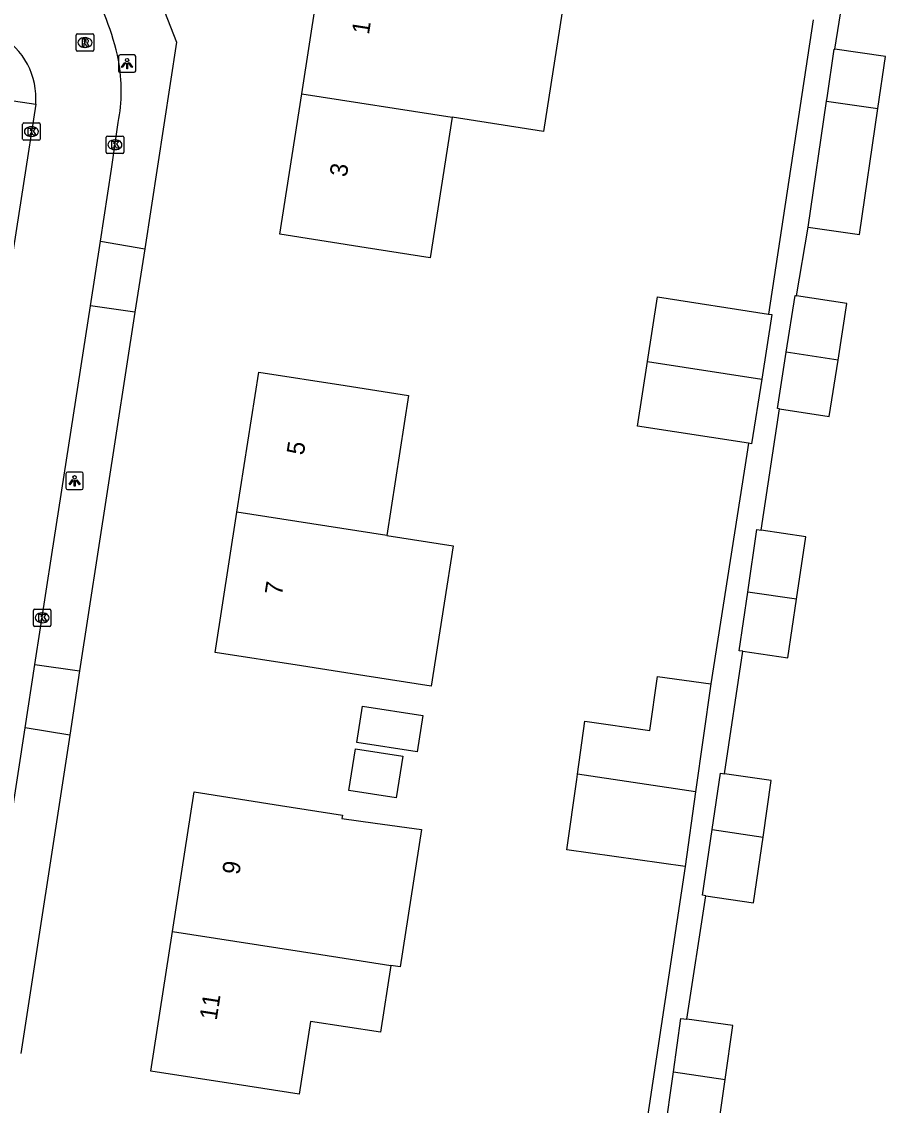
# Model space of a CAD drawing. Extents: x 161486 to 162249, y 379484 to 380829.
# Drawn here: x 162087.4 to 162137.6, y 380409.6 to 380471.6 of the extents above; entities that cross this region are included whole.
import ezdxf

# ---------------------------------------------------------------- set-up
doc = ezdxf.new("R2010")
doc.units = 0
for name, color, linetype in [('IMGEO_Kolk', 7, 'Continuous'), ('IMGEO_Lichtpunt', 7, 'Continuous'), ('IMGEO_Pand', 7, 'Continuous'), ('IMGEO_Pand_nummerreeks', 7, 'Continuous'), ('IMGEO_Rijbaan_lokaal_open', 7, 'Continuous'), ('IMGEO_Rioolput', 7, 'Continuous'), ('IMGEO_Voetpad_open', 7, 'Continuous')]:
    doc.layers.add(name, color=color, linetype=linetype)

msp = doc.modelspace()

# ---------------------------------------------------------------- linework, layer by layer
at = {"layer": 'IMGEO_Kolk'}
for p, q in [((162087.491, 380465.787), (162088.343, 380465.787)), ((162087.416, 380464.861), (162087.416, 380465.713)), ((162087.904, 380465.567), (162087.929, 380465.567)), ((162088.417, 380465.713), (162088.417, 380464.861)), ((162088.343, 380464.787), (162087.491, 380464.787)), ((162087.927, 380465.007), (162087.902, 380465.007)), ((162092.2, 380464.107), (162092.2, 380464.959)), ((162092.275, 380465.033), (162093.127, 380465.033)), ((162092.688, 380464.813), (162092.713, 380464.813)), ((162093.201, 380464.959), (162093.201, 380464.107)), ((162093.127, 380464.033), (162092.275, 380464.033)), ((162092.711, 380464.253), (162092.686, 380464.253)), ((162088.03, 380437.037), (162088.03, 380437.889)), ((162088.105, 380437.963), (162088.957, 380437.963)), ((162089.031, 380437.889), (162089.031, 380437.037)), ((162088.518, 380437.743), (162088.543, 380437.743)), ((162088.957, 380436.963), (162088.105, 380436.963)), ((162088.541, 380437.183), (162088.516, 380437.183))]:
    msp.add_line(p, q, dxfattribs=at)
for points in [[(162087.491, 380465.787), (162088.343, 380465.787)], [(162087.416, 380464.861), (162087.416, 380465.713)], [(162087.737, 380465.487), (162087.86, 380465.487), (162087.86, 380465.336), (162087.99, 380465.487), (162088.154, 380465.487), (162088.008, 380465.336), (162088.161, 380465.087), (162088.009, 380465.087), (162087.924, 380465.251), (162087.86, 380465.184), (162087.86, 380465.087), (162087.737, 380465.087), (162087.737, 380465.487)], [(162088.417, 380465.713), (162088.417, 380464.861)], [(162088.343, 380464.787), (162087.491, 380464.787)], [(162092.2, 380464.107), (162092.2, 380464.959)], [(162092.275, 380465.033), (162093.127, 380465.033)], [(162092.521, 380464.733), (162092.644, 380464.733), (162092.644, 380464.582), (162092.774, 380464.733), (162092.938, 380464.733), (162092.792, 380464.582), (162092.945, 380464.333), (162092.793, 380464.333), (162092.708, 380464.497), (162092.644, 380464.43), (162092.644, 380464.333), (162092.521, 380464.333), (162092.521, 380464.733)], [(162093.201, 380464.959), (162093.201, 380464.107)], [(162093.127, 380464.033), (162092.275, 380464.033)], [(162088.03, 380437.037), (162088.03, 380437.889)], [(162088.105, 380437.963), (162088.957, 380437.963)], [(162089.031, 380437.889), (162089.031, 380437.037)], [(162088.351, 380437.663), (162088.474, 380437.663), (162088.474, 380437.512), (162088.604, 380437.663), (162088.768, 380437.663), (162088.622, 380437.512), (162088.775, 380437.263), (162088.623, 380437.263), (162088.538, 380437.427), (162088.474, 380437.36), (162088.474, 380437.263), (162088.351, 380437.263), (162088.351, 380437.663)], [(162088.957, 380436.963), (162088.105, 380436.963)]]:
    msp.add_lwpolyline(points, dxfattribs=at)
for centre, start, end in [((162087.493, 380465.711), 91.55205, 178.44795), ((162087.493, 380465.711), 91.55205, 178.44795), ((162088.341, 380465.711), 1.55205, 88.44795), ((162088.341, 380465.711), 1.55205, 88.44795), ((162087.493, 380464.863), 181.55205, 268.44795), ((162087.493, 380464.863), 181.55205, 268.44795), ((162088.341, 380464.863), 271.55205, 358.44795), ((162088.341, 380464.863), 271.55205, 358.44795), ((162092.277, 380464.957), 91.55205, 178.44795), ((162092.277, 380464.957), 91.55205, 178.44795), ((162093.125, 380464.957), 1.55205, 88.44795), ((162093.125, 380464.957), 1.55205, 88.44795), ((162092.277, 380464.109), 181.55205, 268.44795), ((162092.277, 380464.109), 181.55205, 268.44795), ((162093.125, 380464.109), 271.55205, 358.44795), ((162093.125, 380464.109), 271.55205, 358.44795), ((162088.107, 380437.887), 91.55205, 178.44795), ((162088.107, 380437.887), 91.55205, 178.44795), ((162088.955, 380437.887), 1.55205, 88.44795), ((162088.955, 380437.887), 1.55205, 88.44795), ((162088.107, 380437.039), 181.55205, 268.44795), ((162088.107, 380437.039), 181.55205, 268.44795), ((162088.955, 380437.039), 271.55205, 358.44795), ((162088.955, 380437.039), 271.55205, 358.44795)]:
    msp.add_arc(centre, 0.0765, start, end, dxfattribs=at)
for centre, major_axis, ratio, start_param, end_param in [((162087.903, 380465.287), (-0.387, 0.002), 0.722429, 4.712389, 7.853982), ((162087.928, 380465.287), (-0.39, 0.002), 0.717154, 1.570796, 4.712389), ((162092.687, 380464.533), (-0.387, 0.002), 0.722429, 4.712389, 7.853982), ((162092.712, 380464.533), (-0.39, 0.002), 0.717154, 1.570796, 4.712389), ((162088.517, 380437.463), (-0.387, 0.002), 0.722429, 4.712389, 7.853982), ((162088.542, 380437.463), (-0.39, 0.002), 0.717154, 1.570796, 4.712389)]:
    msp.add_ellipse(centre, major_axis=major_axis, ratio=ratio, start_param=start_param, end_param=end_param, dxfattribs=at)
at = {"layer": 'IMGEO_Lichtpunt'}
for p, q in [((162092.894, 380469.58), (162092.894, 380468.773)), ((162092.894, 380469.58), (162092.894, 380468.773)), ((162093.796, 380469.675), (162092.988, 380469.675)), ((162093.796, 380469.675), (162092.988, 380469.675)), ((162093.89, 380468.773), (162093.89, 380469.58)), ((162093.89, 380468.773), (162093.89, 380469.58)), ((162092.988, 380468.679), (162093.796, 380468.679)), ((162092.988, 380468.679), (162093.796, 380468.679)), ((162089.889, 380445.703), (162089.889, 380444.896)), ((162089.889, 380445.703), (162089.889, 380444.896)), ((162090.791, 380445.798), (162089.983, 380445.798)), ((162090.791, 380445.798), (162089.983, 380445.798)), ((162090.885, 380444.896), (162090.885, 380445.703)), ((162090.885, 380444.896), (162090.885, 380445.703)), ((162089.983, 380444.802), (162090.791, 380444.802)), ((162089.983, 380444.802), (162090.791, 380444.802))]:
    msp.add_line(p, q, dxfattribs=at)
for points in [[(162093.268, 380469.244), (162093.307, 380469.216), (162093.119, 380468.954), (162093.081, 380468.981), (162093.268, 380469.244)], [(162093.37, 380469.196), (162093.417, 380469.196), (162093.417, 380468.874), (162093.37, 380468.874), (162093.37, 380469.196)], [(162093.48, 380469.216), (162093.518, 380469.243), (162093.705, 380468.981), (162093.666, 380468.953), (162093.48, 380469.216)], [(162090.263, 380445.367), (162090.302, 380445.339), (162090.114, 380445.077), (162090.076, 380445.104), (162090.263, 380445.367)], [(162090.475, 380445.339), (162090.513, 380445.366), (162090.7, 380445.104), (162090.661, 380445.076), (162090.475, 380445.339)], [(162090.365, 380445.319), (162090.412, 380445.319), (162090.412, 380444.997), (162090.365, 380444.997), (162090.365, 380445.319)]]:
    msp.add_lwpolyline(points, dxfattribs=at)
for centre in [(162093.393, 380469.378), (162090.388, 380445.501)]:
    msp.add_circle(centre, 0.0994, dxfattribs=at)
for centre, start, end in [((162092.988, 380469.58), 90, 180), ((162092.988, 380469.58), 90, 180), ((162093.796, 380469.58), 0, 90), ((162093.796, 380469.58), 0, 90), ((162092.988, 380468.773), 180, 270), ((162092.988, 380468.773), 180, 270), ((162093.796, 380468.773), 270, 0), ((162093.796, 380468.773), 270, 360), ((162089.983, 380445.703), 90, 180), ((162089.983, 380445.703), 90, 180), ((162090.791, 380445.703), 0, 90), ((162090.791, 380445.703), 0, 90), ((162089.983, 380444.896), 180, 270), ((162089.983, 380444.896), 180, 270), ((162090.791, 380444.896), 270, 0), ((162090.791, 380444.896), 270, 360)]:
    msp.add_arc(centre, 0.0946, start, end, dxfattribs=at)
at = {"layer": 'IMGEO_Pand'}
for points in [[(162103.391, 380467.45), (162104.642, 380475.49), (162109.583, 380474.721), (162113.249, 380474.151), (162113.048, 380472.859), (162114.73, 380472.597), (162115.031, 380474.532), (162118.577, 380473.981), (162117.226, 380465.298), (162111.998, 380466.111)], [(162133.436, 380467.035), (162133.463, 380467.22), (162133.874, 380470.013), (162133.908, 380470.008)], [(162136.37, 380466.603), (162136.808, 380469.581), (162133.908, 380470.008)], [(162111.998, 380466.111), (162110.747, 380458.069), (162107.08, 380458.639), (162102.139, 380459.408), (162103.391, 380467.45)], [(162103.391, 380467.45), (162111.998, 380466.111)], [(162132.375, 380459.825), (162133.436, 380467.035)], [(162133.436, 380467.035), (162136.37, 380466.603)], [(162132.375, 380459.825), (162135.309, 380459.393), (162136.37, 380466.603)], [(162131.127, 380452.672), (162131.63, 380455.901), (162131.712, 380455.888)], [(162134.085, 380452.212), (162134.587, 380455.441), (162131.712, 380455.888)], [(162123.181, 380452.133), (162123.756, 380455.828), (162130.106, 380454.84)], [(162130.106, 380454.84), (162130.293, 380454.811), (162129.718, 380451.115)], [(162130.736, 380449.427), (162130.624, 380449.444), (162131.127, 380452.672)], [(162130.736, 380449.427), (162133.582, 380448.983), (162134.085, 380452.212)], [(162134.085, 380452.212), (162131.127, 380452.672)], [(162099.68, 380443.5), (162100.928, 380451.524), (162105.869, 380450.755), (162109.502, 380450.189), (162108.253, 380442.164)], [(162128.958, 380447.449), (162122.606, 380448.437), (162123.181, 380452.133)], [(162123.181, 380452.133), (162129.718, 380451.115)], [(162129.718, 380451.115), (162129.143, 380447.42), (162128.958, 380447.449)], [(162108.253, 380442.164), (162112.054, 380441.572), (162111.545, 380438.306), (162110.804, 380433.548), (162107.005, 380434.14), (162103.372, 380434.706), (162098.431, 380435.475), (162099.68, 380443.5)], [(162108.253, 380442.164), (162099.68, 380443.5)], [(162128.922, 380438.935), (162129.448, 380442.509), (162129.686, 380442.474)], [(162131.71, 380438.523), (162132.236, 380442.098), (162129.686, 380442.474)], [(162128.64, 380435.548), (162128.428, 380435.579), (162128.922, 380438.935)], [(162128.64, 380435.548), (162131.216, 380435.168), (162131.71, 380438.523)], [(162131.71, 380438.523), (162128.922, 380438.935)], [(162119.172, 380428.517), (162119.595, 380431.538), (162123.316, 380431.017), (162123.748, 380434.105), (162126.8, 380433.678)], [(162126.8, 380433.678), (162125.935, 380427.495)], [(162110.002, 380429.791), (162106.539, 380430.33), (162106.863, 380432.413), (162110.326, 380431.874), (162110.002, 380429.791)], [(162108.801, 380427.162), (162106.087, 380427.585), (162106.458, 380429.969), (162109.172, 380429.547), (162108.801, 380427.162)], [(162125.339, 380423.232), (162118.565, 380424.18), (162119.13, 380428.217), (162119.172, 380428.517)], [(162125.935, 380427.495), (162119.172, 380428.517)], [(162126.885, 380425.343), (162127.36, 380428.572), (162127.581, 380428.539)], [(162129.793, 380424.916), (162130.269, 380428.144), (162127.581, 380428.539)], [(162095.996, 380419.508), (162097.238, 380427.493), (162102.179, 380426.725), (162105.721, 380426.174), (162105.691, 380425.981), (162107.584, 380425.716), (162110.253, 380425.343), (162109.031, 380417.481), (162108.492, 380417.565)], [(162125.935, 380427.495), (162125.339, 380423.232)], [(162126.519, 380421.559), (162126.332, 380421.587), (162126.885, 380425.343)], [(162126.519, 380421.559), (162129.24, 380421.159), (162129.793, 380424.916)], [(162126.885, 380425.343), (162129.793, 380424.916)], [(162108.492, 380417.565), (162107.897, 380413.74), (162103.883, 380414.364), (162103.235, 380410.202), (162099.694, 380410.753), (162094.753, 380411.521), (162095.996, 380419.508)], [(162095.996, 380419.508), (162104.478, 380418.189), (162108.492, 380417.565)], [(162124.66, 380411.481), (162125.087, 380414.54), (162125.432, 380414.492)], [(162127.625, 380411.044), (162128.056, 380414.125), (162125.432, 380414.492)], [(162124.405, 380407.814), (162124.152, 380407.849), (162124.66, 380411.481)], [(162124.66, 380411.481), (162127.625, 380411.044)], [(162124.405, 380407.814), (162127.12, 380407.434), (162127.625, 380411.044)]]:
    msp.add_lwpolyline(points, dxfattribs=at)
at = {"layer": 'IMGEO_Rijbaan_lokaal_open'}
for points in [[(162088.161, 380466.855), (162086.762, 380457.785), (162086.334, 380454.996)], [(162091.862, 380459.02), (162092.499, 380463.141), (162092.883, 380465.808)], [(162091.291, 380455.319), (162091.862, 380459.02)], [(162088.115, 380434.791), (162089.09, 380441.076), (162091.291, 380455.319)], [(162087.553, 380431.171), (162088.115, 380434.791)], [(162084.667, 380412.462), (162085.816, 380419.971), (162087.553, 380431.171)]]:
    msp.add_lwpolyline(points, dxfattribs=at)
for centre, radius, start, end in [((162076.694, 380465.846), 16.589, 12.24829, 29.12549), ((162084.07, 380467.211), 4.106, 355.02498, 127.07644), ((162083.536, 380467.647), 9.526, 348.8688, 10.39025)]:
    msp.add_arc(centre, radius, start, end, dxfattribs=at)
at = {"layer": 'IMGEO_Rioolput'}
for p, q in [((162090.483, 380469.956), (162090.483, 380470.808)), ((162090.558, 380470.882), (162091.41, 380470.882)), ((162091.484, 380470.808), (162091.484, 380469.956)), ((162090.971, 380470.662), (162090.996, 380470.662)), ((162091.41, 380469.882), (162090.558, 380469.882)), ((162090.994, 380470.102), (162090.969, 380470.102))]:
    msp.add_line(p, q, dxfattribs=at)
for points in [[(162090.483, 380469.956), (162090.483, 380470.808)], [(162090.558, 380470.882), (162091.41, 380470.882)], [(162091.484, 380470.808), (162091.484, 380469.956)], [(162091.072, 380470.58), (162090.82, 380470.582), (162090.82, 380470.182)], [(162090.82, 380470.182), (162090.944, 380470.182), (162090.944, 380470.344), (162090.955, 380470.344)], [(162090.998, 380470.501), (162090.944, 380470.501), (162090.944, 380470.42)], [(162090.944, 380470.42), (162090.996, 380470.42)], [(162091.002, 380470.315), (162091.073, 380470.182), (162091.213, 380470.182), (162091.148, 380470.308)], [(162091.41, 380469.882), (162090.558, 380469.882)]]:
    msp.add_lwpolyline(points, dxfattribs=at)
for centre, radius, start, end in [((162090.56, 380470.806), 0.0765, 91.55205, 178.44795), ((162090.56, 380470.806), 0.0765, 91.55205, 178.44795), ((162091.408, 380470.806), 0.0765, 1.55205, 88.44795), ((162091.408, 380470.806), 0.0765, 1.55205, 88.44795), ((162090.954, 380470.291), 0.0533, 26.02933, 88.69889), ((162090.98, 380470.609), 0.19, 274.7715, 282.96867), ((162091.004, 380470.405), 0.0964, 77.00612, 93.18647), ((162091.018, 380470.462), 0.0378, 276.66336, 79.67722), ((162091.071, 380470.47), 0.109, 350.36119, 89.41601), ((162091.069, 380470.47), 0.112, 277.58423, 350.98172), ((162091.053, 380470.255), 0.108, 29.51342, 73.79051), ((162090.56, 380469.958), 0.0765, 181.55205, 268.44795), ((162090.56, 380469.958), 0.0765, 181.55205, 268.44795), ((162091.408, 380469.958), 0.0765, 271.55205, 358.44795), ((162091.408, 380469.958), 0.0765, 271.55205, 358.44795)]:
    msp.add_arc(centre, radius, start, end, dxfattribs=at)
for centre, major_axis, ratio, start_param, end_param in [((162090.97, 380470.382), (-0.387, 0.002), 0.722429, 4.712389, 7.853982), ((162090.995, 380470.382), (-0.39, 0.002), 0.717154, 1.570796, 4.712389)]:
    msp.add_ellipse(centre, major_axis=major_axis, ratio=ratio, start_param=start_param, end_param=end_param, dxfattribs=at)
at = {"layer": 'IMGEO_Voetpad_open'}
for points in [[(162093.544, 380477.259), (162096.227, 380470.413), (162094.403, 380458.584)], [(162133.908, 380470.008), (162134.481, 380473.597), (162151.539, 380471.087)], [(162132.658, 380471.674), (162130.106, 380454.84)], [(162080.1, 380468.066), (162088.161, 380466.855)], [(162131.712, 380455.888), (162132.375, 380459.825)], [(162091.862, 380459.02), (162094.403, 380458.584)], [(162094.403, 380458.584), (162093.843, 380454.949)], [(162093.843, 380454.949), (162091.291, 380455.319)], [(162093.843, 380454.949), (162090.678, 380434.418)], [(162129.686, 380442.474), (162130.736, 380449.427)], [(162128.958, 380447.449), (162128.86, 380446.817), (162126.8, 380433.678)], [(162127.581, 380428.539), (162128.64, 380435.548)], [(162088.115, 380434.791), (162090.678, 380434.418)], [(162090.678, 380434.418), (162090.113, 380430.753)], [(162090.113, 380430.753), (162087.553, 380431.171)], [(162090.113, 380430.753), (162087.302, 380412.52)], [(162125.339, 380423.232), (162122.317, 380403.215), (162122.106, 380401.847), (162122.095, 380401.775), (162122.888, 380401.658)], [(162125.432, 380414.492), (162126.519, 380421.559)]]:
    msp.add_lwpolyline(points, dxfattribs=at)

# ---------------------------------------------------------------- texts
at = {"layer": 'IMGEO_Pand_nummerreeks'}
for s, rotation, p in [('1', 81.15374, (162107.233, 380470.807)), ('3', 81.15347, (162105.963, 380462.653)), ('5', 81.15648, (162103.502, 380446.736)), ('7', 81.15374, (162102.254, 380438.711)), ('9', 81.15374, (162099.815, 380422.724)), ('11', 81.15655, (162098.52, 380414.395))]:
    msp.add_text(s, height=1, rotation=rotation, dxfattribs=at).set_placement(p)

doc.saveas('drawing.dxf')
